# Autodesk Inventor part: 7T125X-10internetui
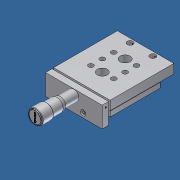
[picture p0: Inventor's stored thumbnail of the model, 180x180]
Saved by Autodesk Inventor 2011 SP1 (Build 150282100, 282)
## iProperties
Created: 2011-05
Part Number: 7T125X-10internetui
Document SubType Name: Modeling
Designer: Darius
Density: 1 g/cm^3
Author: Darius
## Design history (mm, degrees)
feature "Base1"
body "Solid1"
